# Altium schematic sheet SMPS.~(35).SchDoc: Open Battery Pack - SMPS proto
size A3; Date: 26/03/2019; Author: Morgane Vallée - Samuel Lesueur; Revision: 1.0; SheetNumber: 1; SheetTotal: 1
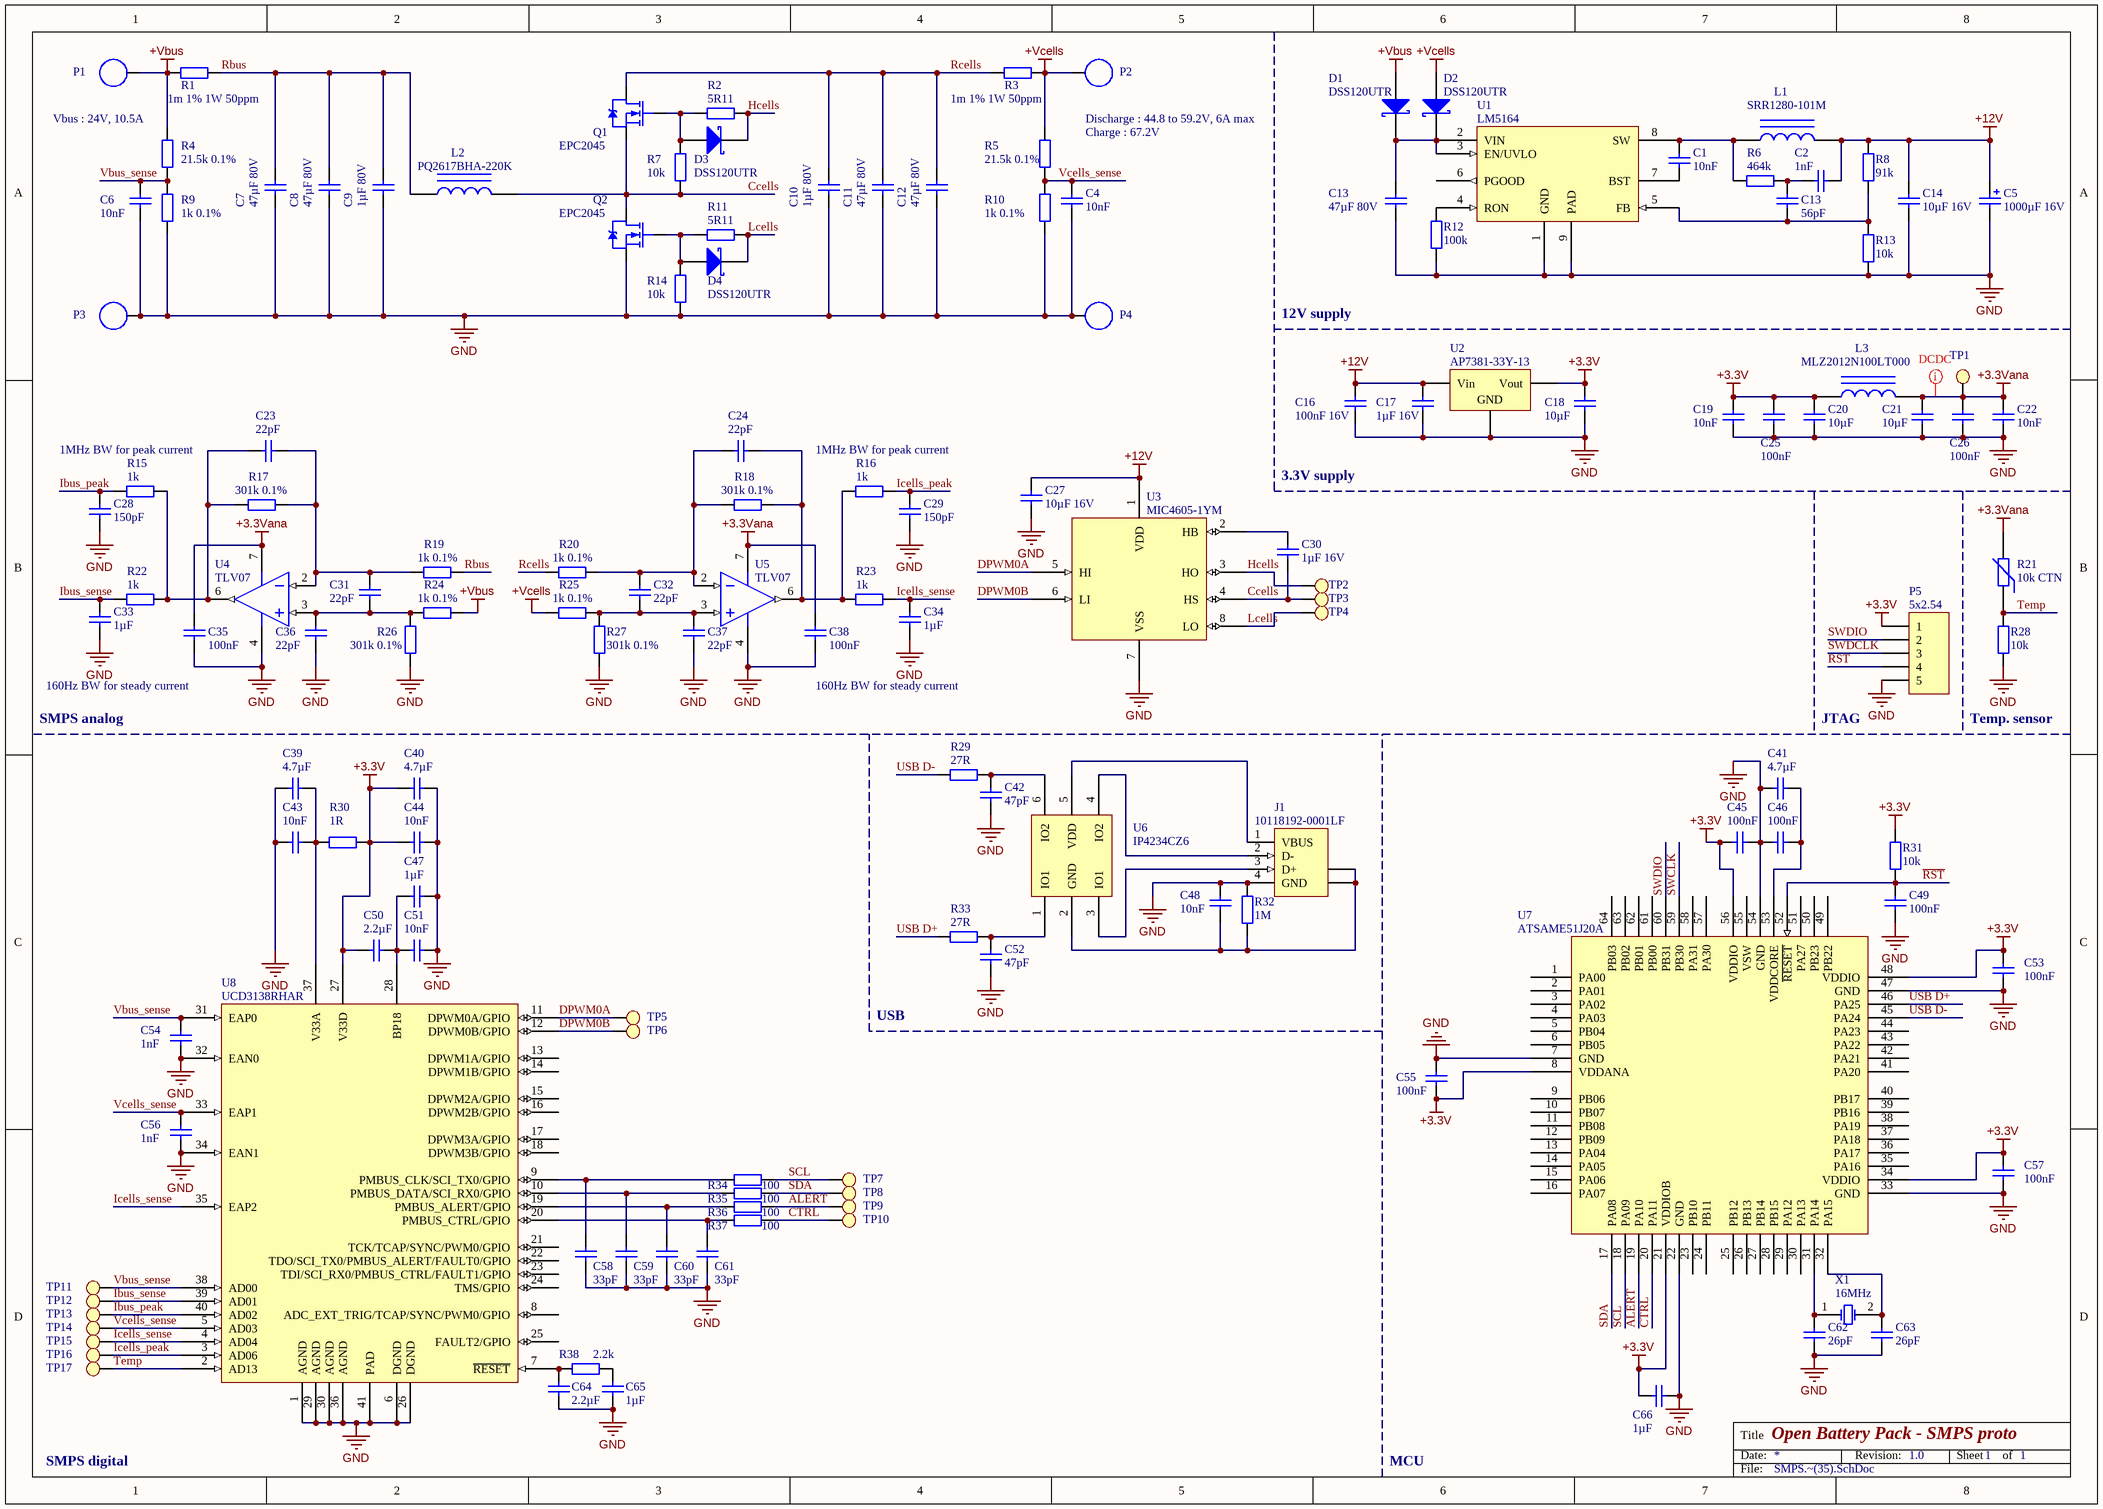
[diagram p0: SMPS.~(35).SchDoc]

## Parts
(Parts that share a designator on the sheet are numbered #1, #2 ... from top to bottom, then left to right.)
C1  10nF  [C0603]
C2  1nF  [C0603]
C4  10nF  [C0603]
C5  1000µF 16V  [CAP AL TH D10 L5 H17.5]
C6  10nF  [C0603]
C7  47µF 80V  [CAP ALUM 10.3MM]
C8  47µF 80V  [CAP ALUM 10.3MM]
C9  1µF 80V  [CAP ALUM 10.3MM]
C10  1µF 80V  [CAP ALUM 10.3MM]
C11  47µF 80V  [CAP ALUM 10.3MM]
C12  47µF 80V  [CAP ALUM 10.3MM]
C13#1  47µF 80V  [CAP ALUM 10.3MM]
C13#2  56pF  [C0603]
C14  10µF 16V  [C0805]
C16  100nF 16V  [C0603]
C17  1µF 16V  [C0805]
C18  10µF  [C0603]
C19  10nF  [C0603]
C20  10µF  [C0603]
C21  10µF  [C0603]
C22  10nF  [C0603]
C23  22pF  [C0603]
C24  22pF  [C0603]
C25  100nF  [C0603]
C26  100nF  [C0603]
C27  10µF 16V  [C0805]
C28  150pF  [C0603]
C29  150pF  [C0603]
C30  1µF 16V  [C0603]
C31  22pF  [C0603]
C32  22pF  [C0603]
C33  1µF  [C0603]
C34  1µF  [C0603]
C35  100nF  [C0603]
C36  22pF  [C0603]
C37  22pF  [C0603]
C38  100nF  [C0603]
C39  4.7µF  [C0603]
C40  4.7µF  [C0603]
C41  4.7µF  [C0603]
C42  47pF  [C0603]
C43  10nF  [C0603]
C44  10nF  [C0603]
C45  100nF  [C0603]
C46  100nF  [C0603]
C47  1µF  [C0603]
C48  10nF  [C0603]
C49  100nF  [C0603]
C50  2.2µF  [C0603]
C51  10nF  [C0603]
C52  47pF  [C0603]
C53  100nF  [C0603]
C54  1nF  [C0603]
C55  100nF  [C0603]
C56  1nF  [C0603]
C57  100nF  [C0603]
C58  33pF  [C0603]
C59  33pF  [C0603]
C60  33pF  [C0603]
C61  33pF  [C0603]
C62  26pF  [C0603]
C63  26pF  [C0603]
C64  2.2µF  [C0603]
C65  1µF  [C0603]
C66  1µF  [C0603]
D1  DSS120UTR  [SOD123F]
D2  DSS120UTR  [SOD123F]
D3  DSS120UTR  [SOD123F]
D4  DSS120UTR  [SOD123F]
J1  10118192-0001LF  [FCI USB 10118193-0001LF]
L1  SRR1280-101M  [SELF_SMD_12.5x12.5]
L2  PQ2617BHA-220K  [SELF_SMD_23.5x22]
L3  MLZ2012N100LT000  [C0805]
P1  PTH  [HOLE_4]  (value not drawn)
P2  PTH  [HOLE_4]  (value not drawn)
P3  PTH  [HOLE_4]  (value not drawn)
P4  PTH  [HOLE_4]  (value not drawn)
P5  5x2.54  [HDR1X5]
Q1  EPC2045  [TO220]
Q2  EPC2045  [TO220]
R1  1m 1% 1W 50ppm  [R1206]
R2  5R11  [R0603]
R3  1m 1% 1W 50ppm  [R1206]
R4  21.5k 0.1%  [R0603]
R5  21.5k 0.1%  [R0603]
R6  464k  [R0603]
R7  10k  [R0603]
R8  91k  [R0603]
R9  1k 0.1%  [R0603]
R10  1k 0.1%  [R0603]
R11  5R11  [R0603]
R12  100k  [R0603]
R13  10k  [R0603]
R14  10k  [R0603]
R15  1k  [R0603]
R16  1k  [R0603]
R17  301k 0.1%  [R0603]
R18  301k 0.1%  [R0603]
R19  1k 0.1%  [R0603]
R20  1k 0.1%  [R0603]
R21  10k CTN  [R0603]
R22  1k  [R0603]
R23  1k  [R0603]
R24  1k 0.1%  [R0603]
R25  1k 0.1%  [R0603]
R26  301k 0.1%  [R0603]
R27  301k 0.1%  [R0603]
R28  10k  [R0603]
R29  27R  [R0603]
R30  1R  [R0603]
R31  10k  [R0603]
R32  1M  [R0603]
R33  27R  [R0603]
R34  100  [R0603]
R35  100  [R0603]
R36  100  [R0603]
R37  100  [R0603]
R38  2.2k  [R0603]
TP1  Test Point  [Test Point]  (value not drawn)
TP2  Test Point  [Test Point]  (value not drawn)
TP3  Test Point  [Test Point]  (value not drawn)
TP4  Test Point  [Test Point]  (value not drawn)
TP5  Test Point  [Test Point]  (value not drawn)
TP6  Test Point  [Test Point]  (value not drawn)
TP7  Test Point  [Test Point]  (value not drawn)
TP8  Test Point  [Test Point]  (value not drawn)
TP9  Test Point  [Test Point]  (value not drawn)
TP10  Test Point  [Test Point]  (value not drawn)
TP11  Test Point  [Test Point]  (value not drawn)
TP12  Test Point  [Test Point]  (value not drawn)
TP13  Test Point  [Test Point]  (value not drawn)
TP14  Test Point  [Test Point]  (value not drawn)
TP15  Test Point  [Test Point]  (value not drawn)
TP16  Test Point  [Test Point]  (value not drawn)
TP17  Test Point  [Test Point]  (value not drawn)
U1  LM5164  [R-PDSO-G8]
U2  AP7381-33Y-13  [ST SOIC-8N]
U3  MIC4605-1YM  [SOIC-8]
U4  TLV07  [SOIC-8]
U5  TLV07  [SOIC-8]
U6  IP4234CZ6  [VISHAY TSOP-6 MO-193C]
U7  ATSAME51J20A  [TQFP-64N]
U8  UCD3138RHAR  [S-PVQFN-N40]
X1  16MHz  [ABRACON ABLS]

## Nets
+3.3V: C18.1 C19.1 C20.1 C25.1 C40.1 C44.1 C45.2 C50.2 C53.2 C55.1 C57.2 C66.2 L3.1 P5.1 R30.1 R31.2 U2.3(Vout) U7.8(VDDANA) U7.21(VDDIOB) U7.34(VDDIO) U7.48(VDDIO) U7.56(VDDIO) U8.27(V33D)
+3.3Vana: C21.1 C22.1 C26.1 C35.1 C38.1 L3.2 R21.2 TP1.1 U4.7(V+) U5.7(V+)
+12V: C2.2 C5.1 C14.1 C16.1 C17.1 C27.2 L1.2 R8.1 U2.1(Vin) U3.1(VDD)
+Vbus: D1.1(A) P1.1 R1.2 R4.1 R24.1
+Vcells: D2.1(A) P2.1 R3.1 R5.1 R25.2
GND: C4.1 C5.2 C6.1 C7.1 C8.1 C9.1 C10.1 C11.1 C12.1 C13#1.1 C14.2 C16.2 C17.2 C18.2 C19.2 C20.2 C21.2 C22.2 C25.2 C26.2 C27.1 C28.1 C29.1 C33.1 C34.1 C35.2 C36.1 C37.1 C38.2 C39.1 C40.2 C41.2 C42.1 C43.1 C44.2 C45.1 C46.2 C47.1 C48.2 C49.1 C51.1 C52.1 C53.1 C54.2 C55.2 C56.2 C57.1 C58.2 C59.2 C60.2 C61.2 C62.1 C63.1 C64.2 C65.2 C66.1 J1.4(GND) P3.1 P4.1 P5.5 Q2.2(S) R9.2 R10.2 R12.2 R13.2 R14.2 R26.2 R27.2 R28.2 R32.1 U1.1(GND) U1.9(PAD) U2.2(GND) U3.7(VSS) U4.4(V-) U5.4(V-) U7.7(GND) U7.22(GND) U7.33(GND) U7.47(GND) U7.54(GND) U8.1(AGND) U8.6(DGND) U8.26(DGND) U8.29(AGND) U8.30(AGND) U8.32(EAN0) U8.34(EAN1) U8.36(AGND) U8.41(PAD)
ALERT: R36.2 TP9.1 U7.19(PA10)
Ccells: C30.1 L2.2 Q1.2(S) Q2.3(D) R7.2 TP3.1 U3.4(HS)
CTRL: R37.2 TP10.1 U7.20(PA11)
DPWM0A: TP5.1 U3.5(HI) U8.11(DPWM0A/GPIO)
DPWM0B: TP6.1 U3.6(LI) U8.12(DPWM0B/GPIO)
Hcells: D3.2(K) R2.1 TP2.1 U3.3(HO)
Ibus_peak: C28.2 R15.2 TP13.1 U8.40(AD02)
Ibus_sense: C33.2 R22.2 TP12.1 U8.39(AD01)
Icells_peak: C29.2 R16.1 TP16.1 U8.3(AD06)
Icells_sense: C34.2 R23.1 TP15.1 U8.4(AD04) U8.35(EAP2)
Lcells: D4.2(K) R11.1 TP4.1 U3.8(LO)
~{RST}: C49.2 P5.4 R31.1 U7.52(~{RESET})
Rbus: C7.2 C8.2 C9.2 L2.1 R1.1 R19.1
Rcells: C10.2 C11.2 C12.2 Q1.3(D) R3.2 R20.2
SCL: R34.2 TP7.1 U7.18(PA09)
SDA: R35.2 TP8.1 U7.17(PA08)
SWCLK: U7.59(PB30)
SWDCLK: P5.3
SWDIO: P5.2 U7.60(PB31)
Temp: R21.1 R28.1 TP17.1 U8.2(AD13)
USB D+: R33.1 U7.46(PA25)
USB D-: R29.1 U7.45(PA24)
Vbus_sense: C6.2 C54.1 R4.2 R9.1 TP11.1 U8.31(EAP0) U8.38(AD00)
Vcells_sense: C4.2 C56.1 R5.2 R10.1 TP14.1 U8.5(AD03) U8.33(EAP1)
NetC1_1: C1.1 L1.1 R6.1 U1.8(SW)
NetC1_2: C1.2 U1.7(BST)
NetC2_1: C2.1 C13#2.2 R6.2
NetC13#1_2: C13#1.2 D1.2(K) D2.2(K) U1.2(VIN) U1.3(EN/UVLO)
NetC13#2_1: C13#2.1 R8.2 R13.1 U1.5(FB)
NetC23_1: C23.1 R15.1 R17.2 R22.1 U4.6(OUT)
NetC23_2: C23.2 C31.2 R17.1 R19.2 U4.2(IN-)
NetC24_1: C24.1 C32.2 R18.2 R20.1 U5.2(IN-)
NetC24_2: C24.2 R16.2 R18.1 R23.2 U5.6(OUT)
NetC30_2: C30.2 U3.2(HB)
NetC31_1: C31.1 C36.2 R24.2 R26.1 U4.3(IN+)
NetC32_1: C32.1 C37.2 R25.1 R27.1 U5.3(IN+)
NetC39_2: C39.2 C43.2 R30.2 U8.37(V33A)
NetC41_1: C41.1 C46.1 U7.53(VDDCORE)
NetC42_2: C42.2 R29.2 U6.6(IO2)
NetC47_2: C47.2 C50.1 C51.2 U8.28(BP18)
NetC48_1: C48.1 J1.5(SHLD) J1.6(SHLD) R32.2 U6.2(GND)
NetC52_2: C52.2 R33.2 U6.1(IO1)
NetC58_1: C58.1 R34.1 U8.9(PMBUS_CLK/SCI_TX0/GPIO)
NetC59_1: C59.1 R35.1 U8.10(PMBUS_DATA/SCI_RX0/GPIO)
NetC60_1: C60.1 R36.1 U8.19(PMBUS_ALERT/GPIO)
NetC61_1: C61.1 R37.1 U8.20(PMBUS_CTRL/GPIO)
NetC62_2: C62.2 U7.31(PA14) X1.1(OSC1)
NetC63_2: C63.2 U7.32(PA15) X1.2(OSC2)
NetC64_1: C64.1 R38.1 U8.7(~{RESET})
NetC65_1: C65.1 R38.2
NetD3_1: D3.1(A) Q1.1(G) R2.2 R7.1
NetD4_1: D4.1(A) Q2.1(G) R11.2 R14.1
NetJ1_1: J1.1(VBUS) U6.5(VDD)
NetJ1_2: J1.2(D-) U6.4(IO2)
NetJ1_3: J1.3(D+) U6.3(IO1)
NetR12_1: R12.1 U1.4(RON)

Not connected (* = marked no-connect by the designer): U1 6(PGOOD); U7 1(PA00) 2(PA01) 3(PA02) 4(PA03) 5(PB04) 6(PB05) 9(PB06) 10(PB07) 11(PB08) 12(PB09) 13(PA04) 14(PA05) 15(PA06) 16(PA07) 23(PB10) 24(PB11) 25(PB12) 26(PB13) 27(PB14) 28(PB15) 29(PA12) 30(PA13) 35(PA16) 36(PA17) 37(PA18) 38(PA19) 39(PB16) 40(PB17) 41(PA20) 42(PA21) 43(PA22) 44(PA23) 49(PB22) 50(PB23) 51(PA27) 55(VSW) 57(PA30) 58(PA31) 61(PB00) 62(PB01) 63(PB02) 64(PB03); U8 8(ADC_EXT_TRIG/TCAP/SYNC/PWM0/GPIO) 13(DPWM1A/GPIO) 14(DPWM1B/GPIO) 15(DPWM2A/GPIO) 16(DPWM2B/GPIO) 17(DPWM3A/GPIO) 18(DPWM3B/GPIO) 21(TCK/TCAP/SYNC/PWM0/GPIO) 22(TDO/SCI_TX0/PMBUS_ALERT/FAULT0/GPIO) 23(TDI/SCI_RX0/PMBUS_CTRL/FAULT1/GPIO) 24(TMS/GPIO) 25(FAULT2/GPIO)

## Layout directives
net class DCDC: +3.3Vana

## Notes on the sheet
- (near R4) Vbus : 24V, 10.5A
- Discharge : 44.8 to 59.2V, 6A max
- Charge : 67.2V
- 12V supply
- 1MHz BW for peak current
- 3.3V supply
- SMPS analog
- 160Hz BW for steady current
- JTAG
- Temp. sensor
- USB
- SMPS digital
- MCU

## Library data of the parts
C1 C2 C4 C6-C12 C13#1 C13#2 C14 C16-C66 = Cap: Capacitor
C5 = Cap Pol1: Polarized Capacitor (Radial)
D1-D4 = D Schottky: Schottky Diode; pin to pad: 1>1+3
J1 = 1-353576-1: USB 1.1, Right Angle, SMT, A Type, Receptacle, 4 Position, White; pin to pad: 4>5 5>S 6>S
L1-L3 = Inductor Iron: Magnetic-Core Inductor
P1-P4 = PTH: Plated Trough Hole for screew
P5 = Header 5: Header, 5-Pin
Q1 Q2 = MOSFET_N
R1-R20 R22-R38 = Res2: Resistor
R21 = Res Varistor: Varistor (Voltage-Sensitive Resistor)
U1 = LM5164: 100-V Input, 1-A synchronous buck DC/DC converter with ultra-low IQ
U2 = Volt Reg: Voltage Regulator; pin to pad: 1>8 2>2+3+6+7 3>1
U3 = MIC4605-1YM: 85V Half-Bridge MOSFET Driver with Adaptive Dead Time  and Shoot-Through Protection
U4 U5 = TLV07: 36-V Precision,Rail-to-RailOutputOperationalAmplifier
U6 = IP4234CZ6: Single USB 2.0 ESD protection to IEC 61000-4-2 level 4
U8 = UCD3138RHAR: Highly Integrated Digital Controller for Isolated Power with 3 Feedback Loops and 8 DPWM Outputs, 40pins
X1 = XTAL: Crystal Oscillator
